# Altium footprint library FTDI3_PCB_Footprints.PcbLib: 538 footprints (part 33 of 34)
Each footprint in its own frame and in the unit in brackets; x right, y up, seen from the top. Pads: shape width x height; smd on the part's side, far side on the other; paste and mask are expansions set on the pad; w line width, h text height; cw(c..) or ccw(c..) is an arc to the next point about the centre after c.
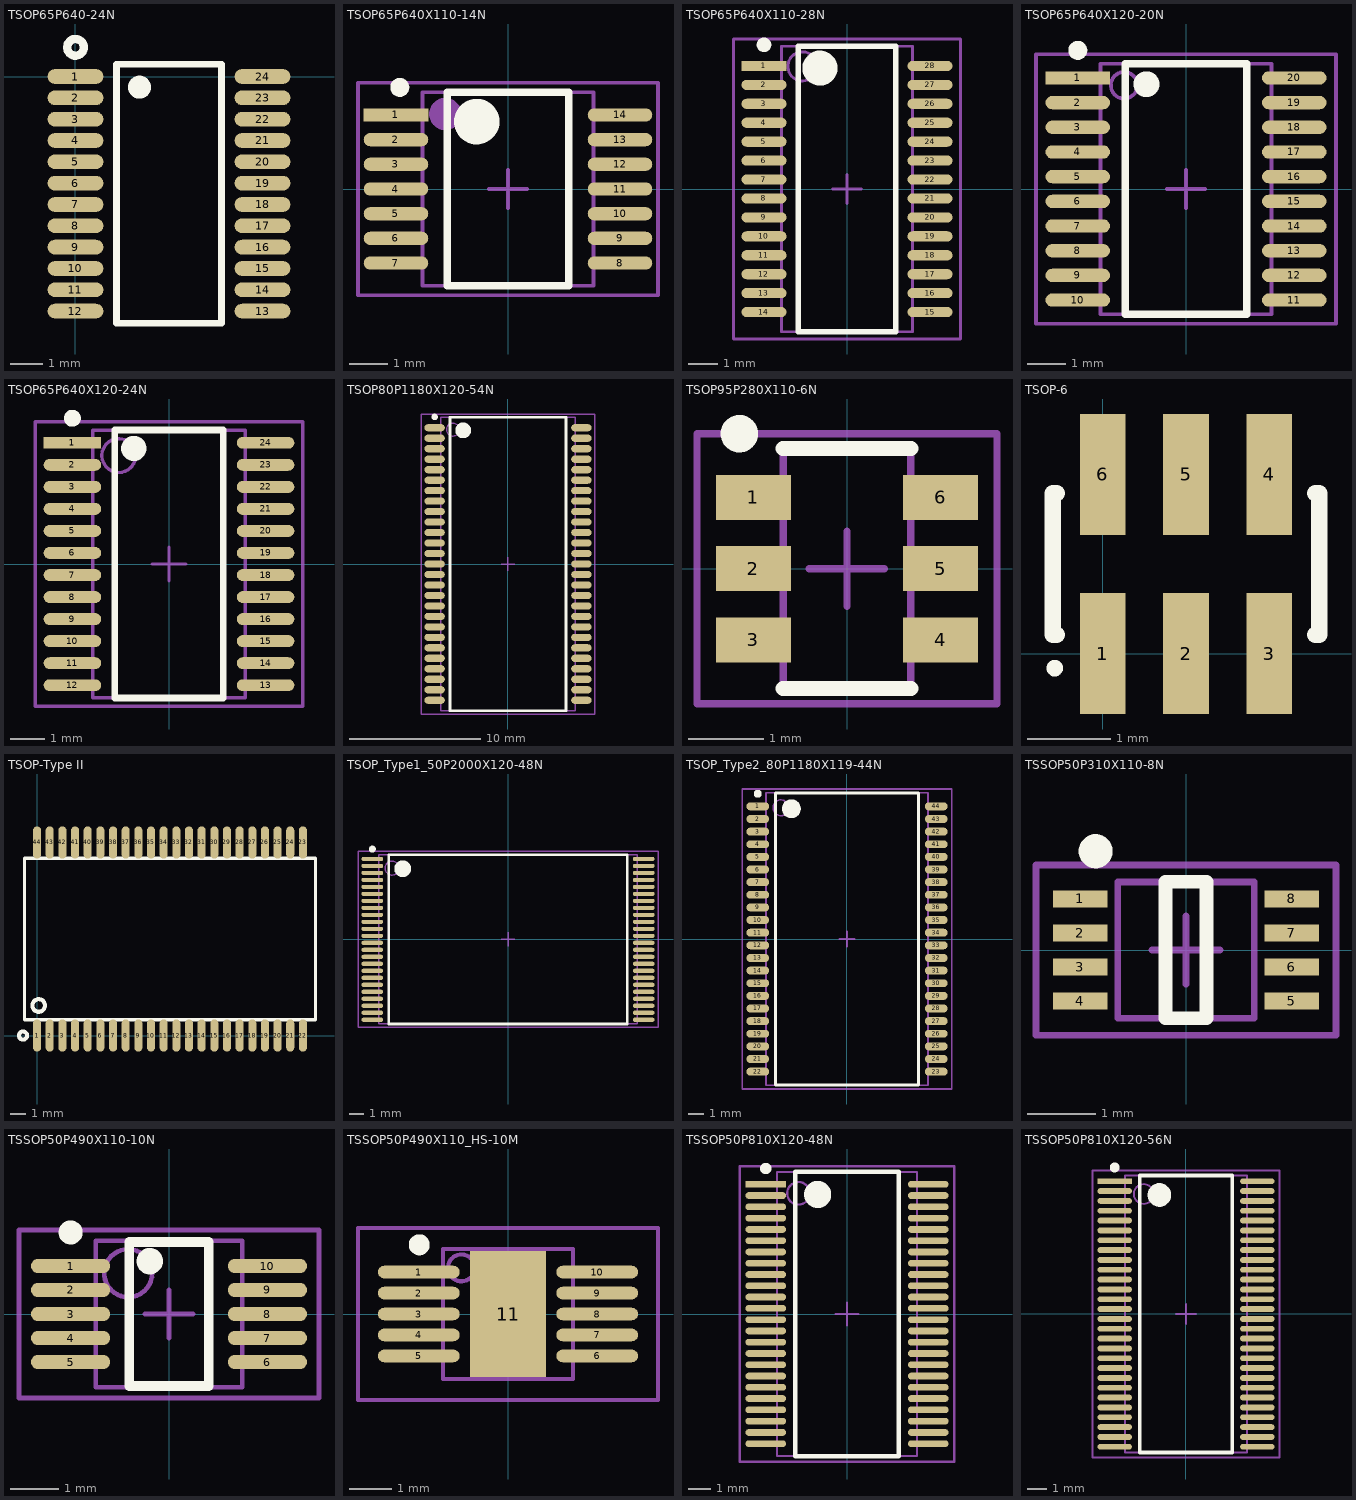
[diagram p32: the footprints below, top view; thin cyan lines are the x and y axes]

## TSOP65P640-24N [mm] "TSOP 24-lead 0.65mm pitch"
height 1.1
pads (24):
  oval 1.7x0.45 smd: 1(0,0) 2(0,-0.65) 3(0,-1.3) 4(0,-1.95) 5(0,-2.6) 6(0,-3.25) 7(0,-3.9) 8(0,-4.55) 9(0,-5.2) 10(0,-5.85) 11(0,-6.5) 12(0,-7.15) 13(5.7,-7.15) 14(5.7,-6.5) 15(5.7,-5.85) 16(5.7,-5.2) 17(5.7,-4.55) 18(5.7,-3.9) 19(5.7,-3.25) 20(5.7,-2.6) 21(5.7,-1.95) 22(5.7,-1.3) 23(5.7,-0.65) 24(5.7,0)
Top Overlay:
  circle w0.254: c0,0.889 r0.254
  circle w0.5: c1.95,-0.325 r0.1
  lines w0.2: 1.25,-7.525 4.45,-7.525 4.45,0.375 1.25,0.375 1.25,-7.525

## TSOP65P640X110-14N [mm] "TSOP, 14-Leads, Body 5.1x4.5mm (max), Pitch 0.65mm, IPC Medium Density"
height 1.1
pads (14):
  rect 1.7x0.35 smd: 1(-2.95,1.95)
  oval 1.7x0.35 smd: 2(-2.95,1.3) 3(-2.95,0.65) 4(-2.95,0) 5(-2.95,-0.65) 6(-2.95,-1.3) 7(-2.95,-1.95) 8(2.95,-1.95) 9(2.95,-1.3) 10(2.95,-0.65) 11(2.95,0) 12(2.95,0.65) 13(2.95,1.3) 14(2.95,1.95)
Top Overlay:
  circle w0.25: c-2.85,2.675 r0.125
  circle w0.6: c-0.825,1.775 r0.3
  lines w0.2: -1.6,-2.55 -1.6,2.55 1.6,2.55 1.6,-2.55 -1.6,-2.55
M13_Assembly_Info:
  circle w0.4: c-1.65,1.975 r0.225
  lines w0.1: -2.25,-2.55 -2.25,2.55 2.25,2.55 2.25,-2.55 -2.25,-2.55
M15_Country_Yard:
  lines w0.1: -0.5,0 0.5,0 ; 0,-0.5 0,0.5 ; -3.95,-2.8 -3.95,2.8 3.95,2.8 3.95,-2.8 -3.95,-2.8
3D body: height 1.1, standoff 0.15, extent -2.25,-2.55 2.25,2.55

## TSOP65P640X110-28N [mm] "TSOP, 28-Leads, Body 9.8x4.5mm (max), Pitch 0.65mm, IPC Medium Density"
height 1.1
pads (28):
  rect 1.55x0.35 smd: 1(-2.85,4.225)
  oval 1.55x0.35 smd: 2(-2.85,3.575) 3(-2.85,2.925) 4(-2.85,2.275) 5(-2.85,1.625) 6(-2.85,0.975) 7(-2.85,0.325) 8(-2.85,-0.325) 9(-2.85,-0.975) 10(-2.85,-1.625) 11(-2.85,-2.275) 12(-2.85,-2.925) 13(-2.85,-3.575) 14(-2.85,-4.225) 15(2.85,-4.225) 16(2.85,-3.575) 17(2.85,-2.925) 18(2.85,-2.275) 19(2.85,-1.625) 20(2.85,-0.975) 21(2.85,-0.325) 22(2.85,0.325) 23(2.85,0.975) 24(2.85,1.625) 25(2.85,2.275) 26(2.85,2.925) 27(2.85,3.575) 28(2.85,4.225)
Top Overlay:
  circle w0.25: c-2.85,4.95 r0.125
  circle w0.6: c-0.93,4.15 r0.3
  lines w0.2: -1.675,-4.9 -1.675,4.9 1.675,4.9 1.675,-4.9 -1.675,-4.9
M13_Assembly_Info:
  circle w0.1: c-1.53,4.21 r0.5
  lines w0.1: -2.25,-4.9 -2.25,4.9 2.25,4.9 2.25,-4.9 -2.25,-4.9
M15_Country_Yard:
  lines w0.1: -0.5,0 0.5,0 ; 0,-0.5 0,0.5 ; -3.9,-5.15 -3.9,5.15 3.9,5.15 3.9,-5.15 -3.9,-5.15
3D body: height 1.1, standoff 0.15, extent -2.25,-4.9 2.25,4.9

## TSOP65P640X120-20N [mm] "TSOP, 20-Leads, Body 6.6x4.5mm (max), Pitch 0.65mm, IPC Medium Density"
height 1.2
pads (20):
  rect 1.7x0.35 smd: 1(-2.85,2.925)
  oval 1.7x0.35 smd: 2(-2.85,2.275) 3(-2.85,1.625) 4(-2.85,0.975) 5(-2.85,0.325) 6(-2.85,-0.325) 7(-2.85,-0.975) 8(-2.85,-1.625) 9(-2.85,-2.275) 10(-2.85,-2.925) 11(2.85,-2.925) 12(2.85,-2.275) 13(2.85,-1.625) 14(2.85,-0.975) 15(2.85,-0.325) 16(2.85,0.325) 17(2.85,0.975) 18(2.85,1.625) 19(2.85,2.275) 20(2.85,2.925)
Top Overlay:
  circle w0.25: c-2.85,3.65 r0.125
  circle w0.6: c-1.04,2.76 r0.04
  lines w0.2: -1.6,-3.3 -1.6,3.3 1.6,3.3 1.6,-3.3 -1.6,-3.3
M13_Assembly_Info:
  circle w0.1: c-1.63,2.73 r0.35
  lines w0.1: -2.25,-3.3 -2.25,3.3 2.25,3.3 2.25,-3.3 -2.25,-3.3
M15_Country_Yard:
  lines w0.1: -0.5,0 0.5,0 ; 0,-0.5 0,0.5 ; -3.95,-3.55 -3.95,3.55 3.95,3.55 3.95,-3.55 -3.95,-3.55
3D body: height 1.2, standoff 0.1, extent -2.25,-3.3 2.25,3.3

## TSOP65P640X120-24N [mm] "TSOP, 24-Leads, Body 7.9x4.5mm (max), Pitch 0.65mm, IPC Medium Density"
height 1.2
pads (24):
  rect 1.7x0.35 smd: 1(-2.85,3.575)
  oval 1.7x0.35 smd: 2(-2.85,2.925) 3(-2.85,2.275) 4(-2.85,1.625) 5(-2.85,0.975) 6(-2.85,0.325) 7(-2.85,-0.325) 8(-2.85,-0.975) 9(-2.85,-1.625) 10(-2.85,-2.275) 11(-2.85,-2.925) 12(-2.85,-3.575) 13(2.85,-3.575) 14(2.85,-2.925) 15(2.85,-2.275) 16(2.85,-1.625) 17(2.85,-0.975) 18(2.85,-0.325) 19(2.85,0.325) 20(2.85,0.975) 21(2.85,1.625) 22(2.85,2.275) 23(2.85,2.925) 24(2.85,3.575)
Top Overlay:
  circle w0.6: c-1.04,3.41 r0.07
  circle w0.25: c-2.85,4.3 r0.125
  lines w0.2: -1.6,-3.95 1.6,-3.95 1.6,3.95 -1.6,3.95 -1.6,-3.95
M13_Assembly_Info:
  circle w0.1: c-1.48,3.2 r0.5
  lines w0.1: -2.25,-3.95 2.25,-3.95 2.25,3.95 -2.25,3.95 -2.25,-3.95
M15_Country_Yard:
  lines w0.1: -0.5,0 0.5,0 ; 0,-0.5 0,0.5 ; -3.95,-4.2 3.95,-4.2 3.95,4.2 -3.95,4.2 -3.95,-4.2
3D body: height 1.2, standoff 0.1, extent -2.25,-3.95 2.25,3.95

## TSOP80P1180X120-54N [mm] "TSOP, 54-Leads, Body 22.4x10.3mm (max), Pitch 0.80mm, IPC Medium Density"
height 1.2
pads (54):
  oval 1.55x0.55 smd: 1(-5.6,10.4) 2(-5.6,9.6) 3(-5.6,8.8) 4(-5.6,8) 5(-5.6,7.2) 6(-5.6,6.4) 7(-5.6,5.6) 8(-5.6,4.8) 9(-5.6,4) 10(-5.6,3.2) 11(-5.6,2.4) 12(-5.6,1.6) 13(-5.6,0.8) 14(-5.6,0) 15(-5.6,-0.8) 16(-5.6,-1.6) 17(-5.6,-2.4) 18(-5.6,-3.2) 19(-5.6,-4) 20(-5.6,-4.8) 21(-5.6,-5.6) 22(-5.6,-6.4) 23(-5.6,-7.2) 24(-5.6,-8) 25(-5.6,-8.8) 26(-5.6,-9.6) 27(-5.6,-10.4) 28(5.6,-10.4) 29(5.6,-9.6) 30(5.6,-8.8) 31(5.6,-8) 32(5.6,-7.2) 33(5.6,-6.4) 34(5.6,-5.6) 35(5.6,-4.8) 36(5.6,-4) 37(5.6,-3.2) 38(5.6,-2.4) 39(5.6,-1.6) 40(5.6,-0.8) 41(5.6,0) 42(5.6,0.8) 43(5.6,1.6) 44(5.6,2.4) 45(5.6,3.2) 46(5.6,4) 47(5.6,4.8) 48(5.6,5.6) 49(5.6,6.4) 50(5.6,7.2) 51(5.6,8) 52(5.6,8.8) 53(5.6,9.6) 54(5.6,10.4)
Top Overlay:
  circle w0.25: c-5.6,11.225 r0.125
  circle w0.6: c-3.425,10.2 r0.3
  lines w0.2: -4.425,-11.2 -4.425,11.2 4.425,11.2 4.425,-11.2 -4.425,-11.2
M13_Assembly_Info:
  circle w0.1: c-4.195,10.26 r0.5
  lines w0.1: -5.145,-11.21 -5.145,11.21 5.145,11.21 5.145,-11.21 -5.145,-11.21
M15_Country_Yard:
  lines w0.1: -0.5,0 0.5,0 ; 0,-0.5 0,0.5 ; -6.625,-11.45 -6.625,11.45 6.625,11.45 6.625,-11.45 -6.625,-11.45
3D body: height 1.2, standoff 0.15, extent -5.145,-11.21 5.145,11.21

## TSOP95P280X110-6N [mm] "TSOP, 6-Leads, Body 3.00x1.50mm, Pitch 0.95mm, IPC Medium Density"
height 1.1
pads (6):
  rect 1x0.6 smd: 1(-1.25,0.95) 2(-1.25,0) 3(-1.25,-0.95) 4(1.25,-0.95) 5(1.25,0) 6(1.25,0.95)
Top Overlay:
  circle w0.25: c-1.435,1.8 r0.125
  lines w0.2: -0.85,-1.6 0.85,-1.6 ; -0.85,1.6 0.85,1.6
M13_Assembly_Info:
  lines w0.1: -0.85,-1.55 -0.85,1.55 0.85,1.55 0.85,-1.55 -0.85,-1.55
M15_Country_Yard:
  lines w0.1: -0.5,0 0.5,0 ; 0,-0.5 0,0.5 ; -2,-1.8 -2,1.8 2,1.8 2,-1.8 -2,-1.8
3D body: height 1.1, standoff 0.1, extent -0.85,-1.55 0.85,1.55

## TSOP-6 [mm] "SOT-457/SC-74; 6 Leads; Body 3.1 x 2.9 mm, inc. leads (LxW max)"
height 1.1
pads (6):
  rect 0.55x1.45 smd: 1(0,0) 2(1,0) 3(2,0) 4(2,2.15) 5(1,2.15) 6(0,2.15)
Top Overlay:
  circle w0.1: c-0.575,-0.175 r0.05
  lines w0.2: -0.55,0.225 -0.6,0.225 -0.6,1.925 -0.55,1.925 ; 2.55,0.225 2.6,0.225 2.6,1.925 2.55,1.925

## TSOP-Type II [mil] "Plastic TSOP Type II"
pads (44):
  oval 20x80 smd: 1(0,0) 2(31.5,0) 3(62.99,0) 4(94.49,0) 5(125.98,0) 6(157.48,0) 7(188.98,0) 8(220.47,0) 9(251.97,0) 10(283.46,0) 11(314.96,0) 12(346.46,0) 13(377.95,0) 14(409.45,0) 15(440.94,0) 16(472.44,0) 17(503.94,0) 18(535.43,0) 19(566.93,0) 20(598.43,0) 21(629.92,0) 22(661.42,0) 23(661.42,480.31) 24(629.92,480.31) 25(598.42,480.31) 26(566.93,480.31) 27(535.43,480.31) 28(503.94,480.31) 29(472.44,480.31) 30(440.94,480.31) 31(409.45,480.31) 32(377.95,480.31) 33(346.46,480.31) 34(314.96,480.31) 35(283.46,480.31) 36(251.97,480.31) 37(220.47,480.31) 38(188.98,480.31) 39(157.48,480.31) 40(125.98,480.31) 41(94.49,480.31) 42(62.99,480.31) 43(31.5,480.31) 44(0,480.31)
Top Overlay:
  circle w10: c3.94,74.8 r15.75
  circle w10: c-34.92,0 r10
  lines w7.87: -31.5,39.37 -31.5,440.94 692.91,440.94 692.91,39.37 -31.5,39.37

## TSOP_Type1_50P2000X120-48N [mm] "TSOP Type 1, 48-Leads, Body 12.1x18.5mm (max), Pitch 0.50mm, IPC Medium Density"
height 1.2
pads (48):
  oval 1.55x0.3 smd: 1(-9.7,5.75) 2(-9.7,5.25) 3(-9.7,4.75) 4(-9.7,4.25) 5(-9.7,3.75) 6(-9.7,3.25) 7(-9.7,2.75) 8(-9.7,2.25) 9(-9.7,1.75) 10(-9.7,1.25) 11(-9.7,0.75) 12(-9.7,0.25) 13(-9.7,-0.25) 14(-9.7,-0.75) 15(-9.7,-1.25) 16(-9.7,-1.75) 17(-9.7,-2.25) 18(-9.7,-2.75) 19(-9.7,-3.25) 20(-9.7,-3.75) 21(-9.7,-4.25) 22(-9.7,-4.75) 23(-9.7,-5.25) 24(-9.7,-5.75) 25(9.7,-5.75) 26(9.7,-5.25) 27(9.7,-4.75) 28(9.7,-4.25) 29(9.7,-3.75) 30(9.7,-3.25) 31(9.7,-2.75) 32(9.7,-2.25) 33(9.7,-1.75) 34(9.7,-1.25) 35(9.7,-0.75) 36(9.7,-0.25) 37(9.7,0.25) 38(9.7,0.75) 39(9.7,1.25) 40(9.7,1.75) 41(9.7,2.25) 42(9.7,2.75) 43(9.7,3.25) 44(9.7,3.75) 45(9.7,4.25) 46(9.7,4.75) 47(9.7,5.25) 48(9.7,5.75)
Top Overlay:
  circle w0.6: c-7.525,5.05 r0.3
  circle w0.25: c-9.7,6.45 r0.125
  lines w0.2: -8.525,-6.05 8.525,-6.05 8.525,6.05 -8.525,6.05 -8.525,-6.05
M13_Assembly_Info:
  circle w0.1: c-8.29,5.09 r0.5
  lines w0.1: -9.24,-6.04 9.24,-6.04 9.24,6.04 -9.24,6.04 -9.24,-6.04
M15_Country_Yard:
  lines w0.1: -0.5,0 0.5,0 ; 0,-0.5 0,0.5 ; -10.725,-6.3 10.725,-6.3 10.725,6.3 -10.725,6.3 -10.725,-6.3
3D body: height 1.2, standoff 0.2, extent -9.24,-6.04 9.24,6.04

## TSOP_Type2_80P1180X119-44N [mm] "TSOP Type 2, 44-Leads, Body 18.5x10.3mm (max), Pitch 0.80mm, IPC Medium Density"
height 1.194
pads (44):
  oval 1.45x0.5 smd: 1(-5.65,8.4) 2(-5.65,7.6) 3(-5.65,6.8) 4(-5.65,6) 5(-5.65,5.2) 6(-5.65,4.4) 7(-5.65,3.6) 8(-5.65,2.8) 9(-5.65,2) 10(-5.65,1.2) 11(-5.65,0.4) 12(-5.65,-0.4) 13(-5.65,-1.2) 14(-5.65,-2) 15(-5.65,-2.8) 16(-5.65,-3.6) 17(-5.65,-4.4) 18(-5.65,-5.2) 19(-5.65,-6) 20(-5.65,-6.8) 21(-5.65,-7.6) 22(-5.65,-8.4) 23(5.65,-8.4) 24(5.65,-7.6) 25(5.65,-6.8) 26(5.65,-6) 27(5.65,-5.2) 28(5.65,-4.4) 29(5.65,-3.6) 30(5.65,-2.8) 31(5.65,-2) 32(5.65,-1.2) 33(5.65,-0.4) 34(5.65,0.4) 35(5.65,1.2) 36(5.65,2) 37(5.65,2.8) 38(5.65,3.6) 39(5.65,4.4) 40(5.65,5.2) 41(5.65,6) 42(5.65,6.8) 43(5.65,7.6) 44(5.65,8.4)
Top Overlay:
  circle w0.6: c-3.525,8.25 r0.3
  circle w0.25: c-5.65,9.2 r0.125
  lines w0.2: -4.525,-9.25 4.525,-9.25 4.525,9.25 -4.525,9.25 -4.525,-9.25
M13_Assembly_Info:
  circle w0.1: c-4.18,8.31 r0.5
  lines w0.1: -5.13,-9.26 5.13,-9.26 5.13,9.26 -5.13,9.26 -5.13,-9.26
M15_Country_Yard:
  lines w0.1: -0.5,0 0.5,0 ; 0,-0.5 0,0.5 ; -6.625,-9.5 6.625,-9.5 6.625,9.5 -6.625,9.5 -6.625,-9.5
3D body: height 1.19, standoff 0.15, extent -5.13,-9.26 5.13,9.26

## TSSOP50P310X110-8N [mm] "TSSOP, 8-Leads, Body 2.0x2.3mm (max), Pitch 0.50mm, IPC Medium Density"
height 1.1
pads (8):
  rect 0.8x0.25 smd: 1(-1.55,0.75) 2(-1.55,0.25) 3(-1.55,-0.25) 4(-1.55,-0.75) 5(1.55,-0.75) 6(1.55,-0.25) 7(1.55,0.25) 8(1.55,0.75)
Top Overlay:
  circle w0.25: c-1.325,1.45 r0.125
  lines w0.2: -0.3,-1 0.3,-1 0.3,1 -0.3,1 -0.3,-1
M13_Assembly_Info:
  lines w0.1: -1,-1 1,-1 1,1 -1,1 -1,-1
M15_Country_Yard:
  lines w0.1: -0.5,0 0.5,0 ; 0,-0.5 0,0.5 ; -2.2,-1.25 2.2,-1.25 2.2,1.25 -2.2,1.25 -2.2,-1.25
3D body: height 1.1, standoff 0.1, extent -1,-1 1,1

## TSSOP50P490X110-10N [mm] "TSSOP, 10-Leads, Body 3.0x3.0mm (max), Pitch 0.50mm, IPC Medium Density"
height 1.1
pads (10):
  oval 1.65x0.3 smd: 1(-2.05,1) 2(-2.05,0.5) 3(-2.05,0) 4(-2.05,-0.5) 5(-2.05,-1) 6(2.05,-1) 7(2.05,-0.5) 8(2.05,0) 9(2.05,0.5) 10(2.05,1)
Top Overlay:
  circle w0.25: c-2.05,1.7 r0.125
  circle w0.35: c-0.4,1.1 r0.1
  lines w0.2: -0.825,-1.5 -0.825,1.5 0.825,1.5 0.825,-1.5 -0.825,-1.5
M13_Assembly_Info:
  circle w0.1: c-0.85,0.85 r0.5
  lines w0.1: -1.525,-1.525 -1.525,1.525 1.525,1.525 1.525,-1.525 -1.525,-1.525
M15_Country_Yard:
  lines w0.1: -0.5,0 0.5,0 ; 0,-0.5 0,0.5 ; -3.125,-1.75 -3.125,1.75 3.125,1.75 3.125,-1.75 -3.125,-1.75
3D body: height 1.1, standoff 0.15, extent -1.525,-1.525 1.525,1.525

## TSSOP50P490X110_HS-10M [mm] "TSSOP, 10-Leads, Body 3.1x3.1mm (max), Pitch 0.50mm, IPC Low Density"
height 1.1
pads (11):
  oval 1.95x0.3 smd: 1(-2.125,1) 2(-2.125,0.5) 3(-2.125,0) 4(-2.125,-0.5) 5(-2.125,-1) 6(2.125,-1) 7(2.125,-0.5) 8(2.125,0) 9(2.125,0.5) 10(2.125,1)
  rect 1.8x3 smd: 11(0,0)
Top Overlay:
  circle w0.25: c-2.115,1.65 r0.125
M13_Assembly_Info:
  circle w0.1: c-1.11,1.1 r0.32
  lines w0.1: -1.55,-1.55 1.55,-1.55 1.55,1.55 -1.55,1.55 -1.55,-1.55
M15_Country_Yard:
  lines w0.1: -0.5,0 0.5,0 ; 0,-0.5 0,0.5 ; -3.575,-2.05 3.575,-2.05 3.575,2.05 -3.575,2.05 -3.575,-2.05
3D body: height 1.1, standoff 0.2, extent -1.55,-1.55 1.55,1.55

## TSSOP50P810X120-48N [mm] "TSSOP, 48-Leads, Body 12.6x6.2mm (max), Pitch 0.50mm, IPC Medium Density"
height 1.2
pads (48):
  rect 1.8x0.3 smd: 1(-3.6,5.75)
  oval 1.8x0.3 smd: 2(-3.6,5.25) 3(-3.6,4.75) 4(-3.6,4.25) 5(-3.6,3.75) 6(-3.6,3.25) 7(-3.6,2.75) 8(-3.6,2.25) 9(-3.6,1.75) 10(-3.6,1.25) 11(-3.6,0.75) 12(-3.6,0.25) 13(-3.6,-0.25) 14(-3.6,-0.75) 15(-3.6,-1.25) 16(-3.6,-1.75) 17(-3.6,-2.25) 18(-3.6,-2.75) 19(-3.6,-3.25) 20(-3.6,-3.75) 21(-3.6,-4.25) 22(-3.6,-4.75) 23(-3.6,-5.25) 24(-3.6,-5.75) 25(3.6,-5.75) 26(3.6,-5.25) 27(3.6,-4.75) 28(3.6,-4.25) 29(3.6,-3.75) 30(3.6,-3.25) 31(3.6,-2.75) 32(3.6,-2.25) 33(3.6,-1.75) 34(3.6,-1.25) 35(3.6,-0.75) 36(3.6,-0.25) 37(3.6,0.25) 38(3.6,0.75) 39(3.6,1.25) 40(3.6,1.75) 41(3.6,2.25) 42(3.6,2.75) 43(3.6,3.25) 44(3.6,3.75) 45(3.6,4.25) 46(3.6,4.75) 47(3.6,5.25) 48(3.6,5.75)
Top Overlay:
  circle w0.6: c-1.3,5.3 r0.3
  circle w0.25: c-3.6,6.45 r0.125
  lines w0.2: -2.3,-6.3 2.3,-6.3 2.3,6.3 -2.3,6.3 -2.3,-6.3
M13_Assembly_Info:
  circle w0.1: c-2.15,5.35 r0.5
  lines w0.1: -3.1,-6.3 3.1,-6.3 3.1,6.3 -3.1,6.3 -3.1,-6.3
M15_Country_Yard:
  lines w0.1: -0.5,0 0.5,0 ; 0,-0.5 0,0.5 ; -4.75,-6.55 4.75,-6.55 4.75,6.55 -4.75,6.55 -4.75,-6.55
3D body: height 1.2, standoff 0.15, extent -3.1,-6.3 3.1,6.3

## TSSOP50P810X120-56N [mm] "TSSOP, 56-Leads, Body 14.1x6.2mm (max), Pitch 0.50mm, IPC Medium Density"
height 1.2
pads (56):
  rect 1.75x0.3 smd: 1(-3.625,6.75)
  oval 1.75x0.3 smd: 2(-3.625,6.25) 3(-3.625,5.75) 4(-3.625,5.25) 5(-3.625,4.75) 6(-3.625,4.25) 7(-3.625,3.75) 8(-3.625,3.25) 9(-3.625,2.75) 10(-3.625,2.25) 11(-3.625,1.75) 12(-3.625,1.25) 13(-3.625,0.75) 14(-3.625,0.25) 15(-3.625,-0.25) 16(-3.625,-0.75) 17(-3.625,-1.25) 18(-3.625,-1.75) 19(-3.625,-2.25) 20(-3.625,-2.75) 21(-3.625,-3.25) 22(-3.625,-3.75) 23(-3.625,-4.25) 24(-3.625,-4.75) 25(-3.625,-5.25) 26(-3.625,-5.75) 27(-3.625,-6.25) 28(-3.625,-6.75) 29(3.625,-6.75) 30(3.625,-6.25) 31(3.625,-5.75) 32(3.625,-5.25) 33(3.625,-4.75) 34(3.625,-4.25) 35(3.625,-3.75) 36(3.625,-3.25) 37(3.625,-2.75) 38(3.625,-2.25) 39(3.625,-1.75) 40(3.625,-1.25) 41(3.625,-0.75) 42(3.625,-0.25) 43(3.625,0.25) 44(3.625,0.75) 45(3.625,1.25) 46(3.625,1.75) 47(3.625,2.25) 48(3.625,2.75) 49(3.625,3.25) 50(3.625,3.75) 51(3.625,4.25) 52(3.625,4.75) 53(3.625,5.25) 54(3.625,5.75) 55(3.625,6.25) 56(3.625,6.75)
Top Overlay:
  circle w0.25: c-3.625,7.45 r0.125
  circle w0.6: c-1.35,6.05 r0.3
  lines w0.2: -2.35,-7.05 -2.35,7.05 2.35,7.05 2.35,-7.05 -2.35,-7.05
M13_Assembly_Info:
  circle w0.1: c-2.15,6.1 r0.5
  lines w0.1: -3.1,-7.05 -3.1,7.05 3.1,7.05 3.1,-7.05 -3.1,-7.05
M15_Country_Yard:
  lines w0.1: -0.5,0 0.5,0 ; 0,-0.5 0,0.5 ; -4.75,-7.3 -4.75,7.3 4.75,7.3 4.75,-7.3 -4.75,-7.3
3D body: height 1.2, standoff 0.15, extent -3.1,-7.05 3.1,7.05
